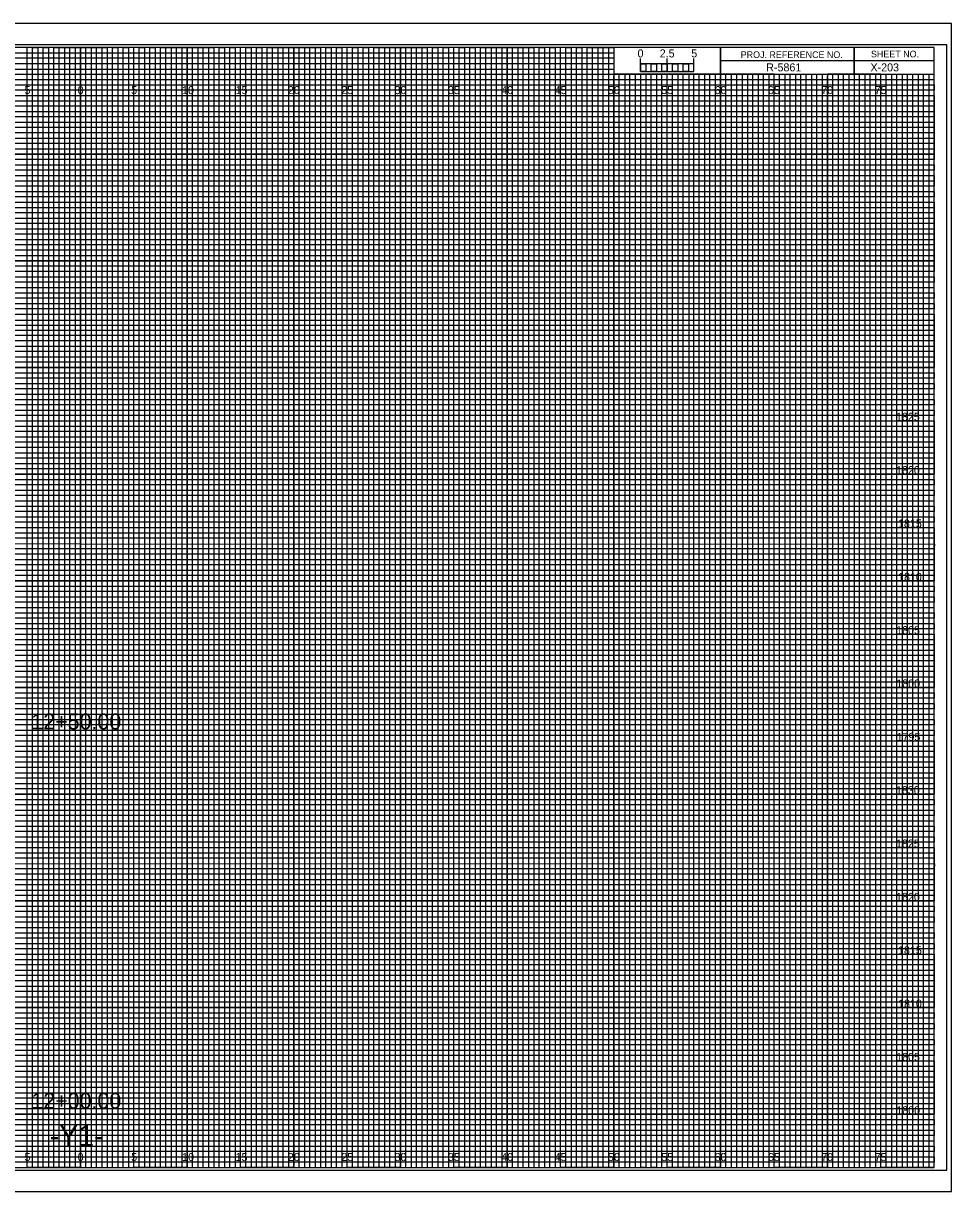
# Model space of a CAD drawing. Extents: x -7 to 162, y -2 to 767.
# Drawn here: x 74.6 to 161.7, y 217.7 to 327.2 of the extents above; entities that cross this region are included whole.
import ezdxf

# ---------------------------------------------------------------- set-up
doc = ezdxf.new("R2010")
doc.units = 0
for name, color, linetype in [('Prop Grid Mask', 7, 'Continuous'), ('Prop XS Alignment Label', 7, 'Continuous'), ('Prop XS Bar Scale Labels', 7, 'Continuous'), ('Prop XS Elevation Labels', 7, 'Continuous'), ('Prop XS Project Number', 7, 'Continuous'), ('Prop XS Sheet Number', 7, 'Continuous'), ('Prop XS Station Labels', 7, 'Continuous'), ('Sheet Cross Section CELL', 7, 'Continuous'), ('Sheet Cross Section Grid Major CELL', 7, 'Continuous'), ('Sheet Cross Section Grid Middle CELL', 7, 'Continuous'), ('Sheet Cross Section Grid Minor 1 CELL', 7, 'Continuous'), ('Sheet Cross Section Grid Minor 2 CELL', 7, 'Continuous'), ('Sheet Cross Section Scale CELL', 7, 'Continuous'), ('Sheet Cutting Line CELL', 7, 'Continuous'), ('Sheet DOT Grid CELL', 7, 'Continuous'), ('Sheet Plot Border Inside CELL', 7, 'Continuous'), ('Sheet Plot Border Outside CELL', 7, 'Continuous')]:
    doc.layers.add(name, color=color, linetype=linetype)

msp = doc.modelspace()

# ---------------------------------------------------------------- linework, layer by layer
at = {"layer": 'Sheet Cross Section CELL'}
for p, q in [((152.5, 325), (152.5, 322.5)), ((152.5, 322.5), (152.5, 325)), ((160, 323.75), (140, 323.75)), ((140, 323.75), (140, 322.5)), ((140, 322.5), (160, 322.5))]:
    msp.add_line(p, q, dxfattribs=at)
for points in [[(160, 325), (0, 325), (0, 220), (160, 220)], [(140, 325), (130, 325), (130, 322.51), (140, 322.51)], [(160, 325), (140, 325), (140, 322.5), (160, 322.5)]]:
    msp.add_lwpolyline(points, close=True, dxfattribs=at)
at = {"layer": 'Sheet Cross Section Grid Major CELL'}
for p, q in [((75, 325), (70, 325)), ((75, 220), (75, 325)), ((85, 325), (80, 325)), ((80, 325), (80, 220)), ((85, 220), (85, 325)), ((95, 325), (90, 325)), ((90, 325), (90, 220)), ((95, 220), (95, 325)), ((105, 325), (100, 325)), ((100, 325), (100, 220)), ((105, 220), (105, 325)), ((115, 325), (110, 325)), ((110, 325), (110, 220)), ((115, 220), (115, 325)), ((125, 325), (120, 325)), ((120, 325), (120, 220)), ((125, 220), (125, 325)), ((130, 325), (130, 220)), ((135, 220), (135, 322.5)), ((145, 322.5), (140, 322.5)), ((140, 322.5), (140, 220)), ((145, 220), (145, 322.5)), ((155, 322.5), (150, 322.5)), ((150, 322.5), (150, 220)), ((155, 220), (155, 322.5)), ((80, 220), (75, 220)), ((90, 220), (85, 220)), ((100, 220), (95, 220)), ((110, 220), (105, 220)), ((120, 220), (115, 220)), ((130, 220), (125, 220)), ((140, 220), (135, 220)), ((150, 220), (145, 220)), ((160, 220), (155, 220)), ((160, 220), (160, 220))]:
    msp.add_line(p, q, dxfattribs=at)
for points in [[(0, 320), (160, 320), (160, 315), (0, 315)], [(0, 310), (160, 310), (160, 305), (0, 305)], [(0, 300), (160, 300), (160, 295), (0, 295)], [(0, 290), (160, 290), (160, 285), (0, 285)], [(0, 280), (160, 280), (160, 275), (0, 275)], [(0, 270), (160, 270), (160, 265), (0, 265)], [(0, 260), (160, 260), (160, 255), (0, 255)], [(0, 250), (160, 250), (160, 245), (0, 245)], [(0, 240), (160, 240), (160, 235), (0, 235)], [(0, 230), (160, 230), (160, 225), (0, 225)]]:
    msp.add_lwpolyline(points, dxfattribs=at)
at = {"layer": 'Sheet Cross Section Grid Middle CELL'}
for points in [[(72.5, 220), (77.5, 220), (77.5, 325), (82.5, 325), (82.5, 220), (87.5, 220), (87.5, 325), (92.5, 325), (92.5, 220), (97.5, 220), (97.5, 325), (102.5, 325), (102.5, 220), (107.5, 220), (107.5, 325), (112.5, 325), (112.5, 220), (117.5, 220), (117.5, 325), (122.5, 325), (122.5, 220), (127.5, 220), (127.5, 325), (129.97, 325), (130, 325), (130, 322.5), (132.5, 322.5), (132.5, 220), (137.5, 220), (137.5, 322.5), (142.5, 322.5), (142.5, 220), (147.5, 220), (147.5, 322.5), (152.5, 322.5), (152.5, 220), (157.5, 220), (157.5, 322.5)], [(0, 322.5), (137.5, 322.5)], [(0, 312.5), (160, 312.5), (160, 317.5), (0, 317.5)], [(0, 302.5), (160, 302.5), (160, 307.5), (0, 307.5)], [(0, 292.5), (160, 292.5), (160, 297.5), (0, 297.5)], [(0, 282.5), (160, 282.5), (160, 287.5), (0, 287.5)], [(0, 272.5), (160, 272.5), (160, 277.5), (0, 277.5)], [(0, 262.5), (160, 262.5), (160, 267.5), (0, 267.5)], [(0, 252.5), (160, 252.5), (160, 257.5), (0, 257.5)], [(0, 242.5), (160, 242.5), (160, 247.5), (0, 247.5)], [(0, 232.5), (160, 232.5), (160, 237.5), (0, 237.5)], [(0, 222.5), (160, 222.5), (160, 227.5), (0, 227.5)]]:
    msp.add_lwpolyline(points, dxfattribs=at)
at = {"layer": 'Sheet Cross Section Grid Minor 1 CELL'}
for p, q in [((0, 324.5), (130, 324.5)), ((130, 324.5), (130, 323.99)), ((130, 323.99), (0, 323.99)), ((0, 323.5), (130, 323.5)), ((130, 323.5), (130, 322.94)), ((130, 322.94), (0, 322.94)), ((0, 322), (160, 322))]:
    msp.add_line(p, q, dxfattribs=at)
for points in [[(0, 321.5), (135, 321.5), (160, 321.5), (160, 321), (0, 321)], [(0, 320.5), (160, 320.5), (160, 319.5), (0, 319.5)], [(0, 319), (160, 319), (160, 318.5), (0, 318.49)], [(0, 318), (160, 318), (160, 317), (0, 317)], [(0, 316.5), (160, 316.5), (160, 316), (0, 316)], [(0, 315.5), (160, 315.5), (160, 314.5), (0, 314.5)], [(0, 314), (160, 314), (160, 313.5), (0, 313.5)], [(0, 313), (160, 313), (160, 312), (0, 312)], [(0, 311.5), (160, 311.5), (160, 311), (0, 311)], [(0, 310.5), (160, 310.5), (160, 309.5), (0, 309.5)], [(0, 309), (160, 309), (160, 308.5), (0, 308.5)], [(0, 308), (160, 308), (160, 306.98), (160, 306.5), (160, 306), (0, 306)], [(0, 307), (160, 307), (160, 306.5), (0, 306.5)], [(0, 305.5), (160, 305.5), (160, 304.5), (0, 304.51)], [(0, 304.51), (160, 304.5), (160, 304), (0, 304)], [(0, 303.5), (160, 303.5), (160, 303), (0, 303)], [(0, 302), (160, 302), (160, 301.5), (0, 301.5)], [(0, 301), (160, 301), (160, 300.5), (0, 300.5)], [(-0.04, 299.44), (160, 299.44), (160, 298.94), (-0.04, 298.94)], [(0, 298.5), (160, 298.5), (160, 298), (0, 298)], [(0, 297), (160, 297), (160, 296.5), (0, 296.5)], [(0, 296), (160, 296), (160, 295.5), (0, 295.5)], [(0, 294.5), (160, 294.5), (160, 294), (0, 294)], [(0, 293.5), (160, 293.5), (160, 293), (0, 293)], [(0, 292), (160, 292), (160, 291.5), (0, 291.5)], [(0, 291), (160, 291), (160, 290.5), (0, 290.5)], [(0, 289.5), (160, 289.5), (160, 288.99), (0, 289)], [(0, 288.5), (160, 288.5), (160, 288), (0, 288)], [(0, 287), (160, 287), (160, 286.5), (0, 286.5)], [(0, 286), (160, 286), (160, 285.5), (0, 285.5)], [(0, 284.5), (160, 284.5), (160, 284), (0, 284)], [(0, 283.5), (160, 283.5), (160, 283), (0, 283)], [(0, 282), (160, 282), (160, 281.5), (0, 281.5)], [(0, 281), (160, 281), (160, 280.5), (0, 280.5)], [(0, 279.5), (160, 279.5), (160, 279), (0, 279)], [(0, 278.5), (160.03, 278.45), (160, 278), (0, 278)], [(0, 277), (160, 277), (160, 276.5), (0, 276.5)], [(0, 276), (160, 276), (160, 275.5), (0, 275.5)], [(0, 274.5), (160, 274.5), (160, 274), (0, 274)], [(0, 273.5), (160, 273.5), (160, 273), (0, 273)], [(0, 272), (160, 272), (160, 271.5), (0, 271.5)], [(0, 271), (160, 271), (160, 270.5), (0, 270.5)], [(0, 269.5), (160, 269.5), (160, 269), (0, 269)], [(0, 268.5), (160, 268.5), (160, 268), (0, 268)], [(0, 267), (160, 267), (160, 266.5), (0, 266.5)], [(0, 266), (160, 266), (160, 265.5), (0, 265.5)], [(0, 264.5), (160, 264.5), (160, 264), (0, 264)], [(0, 263.5), (160, 263.5), (160, 263), (0, 263)], [(0, 262), (160, 262), (160, 261.5), (0, 261.5)], [(0, 261), (160, 261), (160, 260.5), (0, 260.5)], [(0, 259.5), (160, 259.5), (160, 258.99), (0, 259)], [(0, 258.5), (160, 258.5), (160, 258), (0, 258)], [(0, 257), (160, 257), (160, 256.5), (0, 256.5)], [(0, 256), (160, 256), (160, 255.5), (0, 255.5)], [(0, 254.5), (160, 254.5), (160, 254), (0, 254)], [(0, 253.5), (160, 253.5), (160, 253), (0, 253)], [(0, 252), (160, 252), (160, 251.5), (0, 251.5)], [(0, 251), (160, 251), (160, 250.5), (0, 250.5)], [(0, 249.5), (160, 249.5), (160, 249), (0, 249)], [(0, 248.5), (160.03, 248.46), (160, 248), (0, 248)], [(0, 247), (160, 247), (160, 246.5), (0, 246.5)], [(0, 246), (160, 246), (160, 245.5), (0, 245.5)], [(0, 244.5), (160, 244.5), (160, 244), (0, 244)], [(0, 243.5), (160, 243.5), (160, 243), (0, 243)], [(0, 242), (160, 242), (160, 241.5), (0, 241.5)], [(0, 241), (160, 241), (160, 240.5), (0, 240.5)], [(0, 239.5), (160, 239.5), (160, 239), (0, 239)], [(0, 238.5), (160, 238.5), (160, 238), (0, 238)], [(0, 237), (160, 237), (160, 236.5), (0, 236.5)], [(0, 236), (160, 236), (160, 235.5), (0, 235.5)], [(0, 234.5), (160, 234.5), (160, 234), (0, 234)], [(0, 233.5), (160, 233.5), (160, 233), (0, 233)], [(0, 232), (160, 232), (160, 231.5), (0, 231.5)], [(0, 231), (160, 231), (160, 230.5), (0, 230.5)], [(0, 229.5), (160, 229.5), (160, 229), (0, 229)], [(0, 228.5), (160, 228.5), (160, 228), (0, 228)], [(0, 227), (160, 227), (160, 226.5), (0, 226.5)], [(0, 226), (160, 226), (160, 225.5), (0, 225.5)], [(0, 224.5), (160, 224.5), (160, 224), (0, 224)], [(0, 223.5), (160, 223.5), (160, 223), (0, 223)], [(0, 222), (160, 222), (160, 221.5), (0, 221.5)], [(0, 221), (160, 221), (160, 220.5), (0, 220.5)]]:
    msp.add_lwpolyline(points, dxfattribs=at)
at = {"layer": 'Sheet Cross Section Grid Minor 2 CELL'}
for p, q in [((133.5, 322.5), (133, 322.5)), ((133, 322.5), (133, 220)), ((133.5, 220), (133.5, 322.5)), ((134.5, 322.5), (134, 322.5)), ((134, 322.5), (134, 220)), ((134.5, 220), (134.5, 322.5)), ((133, 220), (132.5, 220)), ((134, 220), (133.5, 220))]:
    msp.add_line(p, q, dxfattribs=at)
for points in [[(75, 220), (75.5, 220), (75.5, 325), (76, 325), (76, 220)], [(76, 220), (76.5, 220), (76.5, 325), (77, 325), (77, 220)], [(77.5, 220), (78, 220), (78, 325), (78.5, 325), (78.5, 220)], [(78.5, 220), (79, 220), (79, 325), (79.5, 325), (79.5, 220)], [(80, 220), (80.5, 220), (80.5, 325), (81, 325), (81, 220)], [(81, 220), (81.5, 220), (81.5, 325), (82, 325), (82, 220)], [(82.5, 220), (83, 220), (83, 325), (83.5, 325), (83.5, 220)], [(83.5, 220), (84, 220), (84, 325), (84.5, 325), (84.5, 220)], [(85, 220), (85.5, 220), (85.5, 325), (86, 325), (86, 220)], [(86, 220), (86.5, 220), (86.5, 325), (87, 325), (87, 220)], [(87.5, 220), (88, 220), (88, 325), (88.5, 325), (88.5, 220)], [(88.5, 220), (89, 220), (89, 325), (89.5, 325), (89.5, 220)], [(90, 220), (90.5, 220), (90.5, 325), (91, 325), (91, 220)], [(91, 220), (91.5, 220), (91.5, 325), (92, 325), (92, 220)], [(92.5, 220), (93, 220), (93, 325), (93.5, 325), (93.5, 220)], [(93.5, 220), (94, 220), (94, 325), (94.5, 325), (94.5, 220)], [(95, 220), (95.5, 220), (95.5, 325), (96, 325), (96, 220)], [(96, 220), (96.5, 220), (96.5, 325), (97, 325), (97, 220)], [(97.5, 220), (98, 220), (98, 325), (98.5, 325), (98.5, 220)], [(98.5, 220), (99, 220), (99, 325), (99.5, 325), (99.5, 220)], [(100, 220), (100.5, 220), (100.5, 325), (101, 325), (101, 220)], [(101, 220), (101.5, 220), (101.5, 325), (102, 325), (102, 220)], [(102.5, 220), (103, 220), (103, 325), (103.5, 325), (103.5, 220)], [(103.5, 220), (104, 220), (104, 325), (104.5, 325), (104.5, 220)], [(105, 220), (105.5, 220), (105.5, 325), (106, 325), (106, 220)], [(106, 220), (106.5, 220), (106.5, 325), (107, 325), (107, 220)], [(107.5, 220), (108, 220), (108, 325), (108.5, 325), (108.5, 220)], [(108.5, 220), (109, 220), (109, 325), (109.5, 325), (109.5, 220)], [(110, 220), (110.5, 220), (110.5, 325), (111, 325), (111, 220)], [(111, 220), (111.5, 220), (111.5, 325), (112, 325), (112, 220)], [(112.5, 220), (113, 220), (113, 325), (113.5, 325), (113.5, 220)], [(113.5, 220), (114, 220), (114, 325), (114.5, 325), (114.5, 220)], [(115, 220), (115.5, 220), (115.5, 325), (116, 325), (116, 220)], [(116, 220), (116.5, 220), (116.5, 325), (117, 325), (117, 220)], [(117.5, 220), (118, 220), (118, 325), (118.5, 325), (118.5, 220)], [(118.5, 220), (119, 220), (119, 325), (119.5, 325), (119.5, 220)], [(120, 220), (120.5, 220), (120.5, 325), (121, 325), (121, 220)], [(121, 220), (121.5, 220), (121.5, 325), (122, 325), (122, 220)], [(122.5, 220), (123, 220), (123, 325), (123.5, 325), (123.5, 220)], [(123.5, 220), (124, 220), (124, 325), (124.5, 325), (124.5, 220)], [(125, 220), (125.5, 220), (125.5, 325), (126, 325), (126, 220)], [(126, 220), (126.5, 220), (126.5, 325), (127, 325), (127, 220)], [(127.5, 220), (128, 220), (128, 325), (128.5, 325), (128.5, 220)], [(128.5, 220), (129, 220), (129, 325), (129.5, 325), (129.5, 220)], [(130, 220), (130.5, 220), (130.5, 322.5), (131.01, 322.5), (131.01, 220)], [(131, 220), (131.5, 220), (131.5, 322.5), (132, 322.5), (132, 220)], [(135, 220), (135.49, 220), (135.49, 322.5), (136, 322.5), (136, 220)], [(136, 220), (136.5, 220), (136.5, 322.5), (137.03, 322.5), (137.03, 220)], [(137.5, 220), (138, 220), (138, 322.5), (138.5, 322.5), (138.5, 220)], [(138.5, 220), (139, 220), (139, 322.5), (139.5, 322.5), (139.5, 220)], [(140, 220), (140.5, 220), (140.5, 322.5), (141, 322.5), (141, 220)], [(141, 220), (141.5, 220), (141.5, 322.5), (142, 322.5), (142, 220)], [(142.5, 220), (143, 220), (143, 322.5), (143.5, 322.5), (143.5, 220)], [(143.5, 220), (144, 220), (144, 322.5), (144.5, 322.5), (144.5, 220)], [(145, 220), (145.5, 220), (145.5, 322.5), (146, 322.5), (146, 220)], [(146, 220), (146.5, 220), (146.5, 322.5), (147, 322.5), (147, 220)], [(147.5, 220), (148, 220), (148, 322.5), (148.5, 322.5), (148.5, 220)], [(148.5, 220), (149, 220), (149, 322.5), (149.5, 322.5), (149.5, 220)], [(150, 220), (150.5, 220), (150.5, 322.5), (151, 322.5), (151, 220)], [(151, 220), (151.5, 220), (151.5, 322.5), (152, 322.5), (152, 220)], [(152.5, 220), (153, 220), (153, 322.5), (153.5, 322.5), (153.5, 220)], [(153.5, 220), (154, 220), (154, 322.5), (154.5, 322.5), (154.5, 220)], [(155, 220), (155.5, 220), (155.5, 322.5), (156, 322.5), (156, 220)], [(156, 220), (156.5, 220), (156.5, 322.5), (157, 322.5), (157, 220)], [(157.5, 220), (158, 220), (158, 322.5), (158.5, 322.5), (158.5, 220)], [(158.5, 220), (159, 220), (159, 322.5), (159.5, 322.5), (159.5, 220)]]:
    msp.add_lwpolyline(points, dxfattribs=at)
at = {"layer": 'Sheet Cross Section Scale CELL'}
for p, q in [((132.5, 322.75), (132.5, 323.95)), ((132.5, 323.45), (132.5, 323.95)), ((135, 322.75), (135, 323.95)), ((137.5, 322.75), (137.5, 323.95)), ((137.5, 323.45), (137.5, 323.95))]:
    msp.add_line(p, q, dxfattribs=at)
for points in [[(137.5, 323.45), (132.5, 323.45), (132.5, 322.75), (137.5, 322.75)], [(132.5, 323.45), (133, 323.45), (133, 322.75), (132.5, 322.75)], [(133.5, 323.45), (134, 323.45), (134, 322.75), (133.5, 322.75)], [(134.5, 323.45), (135, 323.45), (135, 322.75), (134.5, 322.75)], [(135.5, 323.45), (136, 323.45), (136, 322.75), (135.5, 322.75)], [(136.5, 323.45), (137, 323.45), (137, 322.75), (136.5, 322.75)]]:
    msp.add_lwpolyline(points, close=True, dxfattribs=at)
at = {"layer": 'Sheet Cutting Line CELL'}
for p, q in [((161.65, 327.25), (-6.7, 327.25)), ((-6.7, 217.75), (161.65, 217.75))]:
    msp.add_line(p, q, dxfattribs=at)
at = {"layer": 'Sheet DOT Grid CELL'}
for p, q in [((75, 220), (75, 325)), ((80, 220), (80, 325)), ((85, 220), (85, 325)), ((90, 220), (90, 325)), ((95, 220), (95, 325)), ((100, 220), (100, 325)), ((105, 220), (105, 325)), ((110, 220), (110, 325)), ((115, 220), (115, 325)), ((120, 220), (120, 325)), ((125, 220), (125, 325)), ((130, 220), (130, 322.34)), ((135, 220), (135, 322.34)), ((140, 220), (140, 322.34)), ((145, 220), (145, 322.34)), ((150, 220), (150, 322.34)), ((155, 220), (155, 322.34)), ((0, 320), (160, 320)), ((0, 315), (160, 315)), ((0, 310), (160, 310)), ((0, 305), (160, 305)), ((0, 300), (160, 300)), ((0, 295), (160, 295)), ((0, 290), (160, 290)), ((0, 285), (160, 285)), ((0, 280), (160, 280)), ((0, 275), (160, 275)), ((0, 270), (160, 270)), ((0, 265), (160, 265)), ((0, 260), (160, 260)), ((0, 255), (160, 255)), ((0, 250), (160, 250)), ((0, 245), (160, 245)), ((0, 240), (160, 240)), ((0, 235), (160, 235)), ((0, 230), (160, 230)), ((0, 225), (160, 225))]:
    msp.add_line(p, q, dxfattribs=at)
at = {"layer": 'Sheet Plot Border Inside CELL'}
msp.add_lwpolyline([(-5.4, 219.75), (161.2, 219.75), (161.2, 325.25), (-5.4, 325.25)], close=True, dxfattribs=at)
at = {"layer": 'Sheet Plot Border Outside CELL'}
msp.add_lwpolyline([(-6.7, 217.75), (161.65, 217.75), (161.65, 327.25), (-6.7, 327.25)], close=True, dxfattribs=at)

# ---------------------------------------------------------------- texts
at = {"layer": 'Prop Grid Mask'}
for s, p in [('5', (74.74, 320.62)), ('0', (79.73, 320.62)), ('0', (79.73, 320.62)), ('5', (84.74, 320.62)), ('10', (89.52, 320.62)), ('15', (94.53, 320.62)), ('20', (99.43, 320.62)), ('25', (104.44, 320.62)), ('30', (109.43, 320.62)), ('35', (114.44, 320.62)), ('40', (119.43, 320.62)), ('45', (124.44, 320.62)), ('50', (129.43, 320.62)), ('55', (134.44, 320.62)), ('60', (139.43, 320.62)), ('65', (144.44, 320.62)), ('70', (149.43, 320.62)), ('75', (154.44, 320.62)), ('5', (74.74, 220.62)), ('0', (79.73, 220.62)), ('0', (79.73, 220.62)), ('5', (84.74, 220.62)), ('10', (89.52, 220.62)), ('15', (94.53, 220.62)), ('20', (99.43, 220.62)), ('25', (104.44, 220.62)), ('30', (109.43, 220.62)), ('35', (114.44, 220.62)), ('40', (119.43, 220.62)), ('45', (124.44, 220.62)), ('50', (129.43, 220.62)), ('55', (134.44, 220.62)), ('60', (139.43, 220.62)), ('65', (144.44, 220.62)), ('70', (149.43, 220.62)), ('75', (154.44, 220.62))]:
    msp.add_text(s, height=0.75, dxfattribs=at).set_placement(p)
at = {"layer": 'Prop XS Alignment Label'}
msp.add_text('-Y1-', height=2, dxfattribs=at).set_placement((77.11, 222))
at = {"layer": 'Prop XS Bar Scale Labels'}
for s, p in [('2.5', (134.29, 324.06)), ('5', (137.24, 324.06))]:
    msp.add_text(s, height=0.75, dxfattribs=at).set_placement(p)
at = {"layer": 'Prop XS Elevation Labels'}
for s, p in [('1825', (156.43, 290)), ('1820', (156.44, 285)), ('1815', (156.62, 280)), ('1810', (156.63, 275)), ('1805', (156.45, 270)), ('1800', (156.46, 265)), ('1795', (156.49, 260)), ('1830', (156.43, 255)), ('1825', (156.43, 250)), ('1820', (156.44, 245)), ('1815', (156.62, 240)), ('1810', (156.63, 235)), ('1805', (156.45, 230)), ('1800', (156.46, 225))]:
    msp.add_text(s, height=0.75, dxfattribs=at).set_placement(p)
at = {"layer": 'Prop XS Project Number'}
msp.add_text('R-5861', height=0.75, dxfattribs=at).set_placement((144.27, 322.75))
at = {"layer": 'Prop XS Sheet Number'}
msp.add_text('X-203', height=0.75, dxfattribs=at).set_placement((154.04, 322.75))
at = {"layer": 'Prop XS Station Labels'}
for s, p in [('12+50.00', (75.39, 261.07)), ('12+00.00', (75.39, 225.52))]:
    msp.add_text(s, height=1.5, dxfattribs=at).set_placement(p)
at = {"layer": 'Sheet Cross Section CELL'}
for s, p in [('PROJ. REFERENCE NO.', (141.88, 324)), ('SHEET NO.', (154.09, 324.06))]:
    msp.add_text(s, height=0.625, dxfattribs=at).set_placement(p)
at = {"layer": 'Sheet Cross Section Scale CELL'}
msp.add_text('0', height=0.75, dxfattribs=at).set_placement((132.21, 324.06))

doc.saveas('drawing.dxf')
